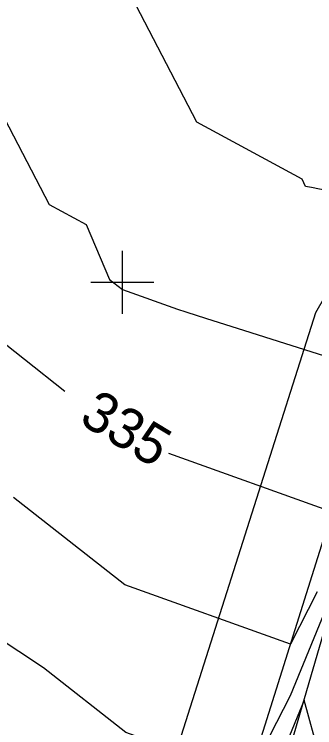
# Model space of a CAD drawing. Extents: x 487096 to 489566, y 221939 to 224454.
# Drawn here: x 488276.8 to 488300.7, y 223456 to 223512.7 of the extents above; entities that cross this region are included whole.
import ezdxf

# ---------------------------------------------------------------- set-up
doc = ezdxf.new("R2010")
doc.units = 0
for name, color, linetype in [('SV_BKLN_EARTH_TOP', 7, 'Continuous'), ('SV_SURF_INDEX_CONTOUR', 7, 'Continuous'), ('SV_SURF_INTER_CONTOUR', 7, 'Continuous'), ('SV_SURF_SPOT', 7, 'Continuous'), ('SV_WATR_INWETF', 7, 'Continuous'), ('SV_WATR_STREAM', 7, 'Continuous')]:
    doc.layers.add(name, color=color, linetype=linetype)

msp = doc.modelspace()

# ---------------------------------------------------------------- linework, layer by layer
at = {"layer": 'SV_BKLN_EARTH_TOP'}
msp.add_lwpolyline([(488285.935, 223421.955), (488304.8, 223481.874)], dxfattribs=at)
at = {"layer": 'SV_SURF_INDEX_CONTOUR'}
for points in [[(488233.223, 223552.139), (488238.155, 223549.446), (488243.978, 223536.925), (488255.675, 223514.417), (488267.055, 223492.613), (488274.354, 223487.789), (488280.81, 223482.721)], [(488289.043, 223477.783), (488302.048, 223473.132)]]:
    msp.add_lwpolyline(points, dxfattribs=at)
at = {"layer": 'SV_SURF_INTER_CONTOUR'}
for points in [[(488261.789, 223531.749), (488279.559, 223497.554), (488282.492, 223495.97), (488284.365, 223491.59), (488285.383, 223490.791), (488289.75, 223489.23), (488290.42, 223489.018), (488291.316, 223488.734), (488292.58, 223488.333), (488294.498, 223487.726), (488297.761, 223486.691), (488304.559, 223484.535)], [(488329.706, 223521.724), (488310.366, 223508.123), (488302.146, 223499.88), (488302.3, 223499.635), (488302.48, 223499.335), (488302.657, 223499.024), (488302.832, 223498.701), (488302.988, 223498.398), (488302.35, 223498.527), (488301.679, 223498.657), (488301.038, 223498.776), (488300.425, 223498.885), (488299.926, 223498.969), (488299.677, 223499.552), (488291.289, 223504.08), (488279.6, 223526.573)], [(488320.594, 223209.107), (488317.309, 223255.078), (488319.07, 223277.176), (488313.215, 223307.684), (488312.007, 223315.85), (488310.013, 223331.587), (488309.153, 223355.183), (488306.035, 223366.994), (488308.318, 223385.059), (488309.639, 223426.754), (488310.11, 223434.831), (488310.416, 223440.004), (488309.761, 223461.164), (488307.732, 223462.227), (488308.954, 223474.096), (488303.636, 223466.041), (488302.905, 223468.698), (488298.726, 223458.507), (488295.426, 223452.101), (488285.665, 223455.591), (488279.114, 223460.734), (488240.248, 223486.418)], [(488316.219, 223209.854), (488313.699, 223245.125), (488316.327, 223278.11), (488311.228, 223304.679), (488309.711, 223314.936), (488307.206, 223334.704), (488306.474, 223354.761), (488302.863, 223368.44), (488304.74, 223383.289), (488306.265, 223431.434), (488306.521, 223435.818), (488306.687, 223438.627), (488306.332, 223450.114), (488303.265, 223451.72), (488303.933, 223458.21), (488301.025, 223453.805), (488299.825, 223458.167), (488296.581, 223450.253), (488292.115, 223441.585), (488285.759, 223443.858), (488281.493, 223447.207), (488226.844, 223483.321)], [(488300.871, 223466.76), (488298.737, 223462.617), (488285.571, 223467.324), (488276.734, 223474.262)]]:
    msp.add_lwpolyline(points, dxfattribs=at)
at = {"layer": 'SV_SURF_SPOT'}
for p, q in [((488285.378, 223488.866), (488285.378, 223493.868)), ((488282.877, 223491.367), (488287.879, 223491.367)), ((488285.378, 223491.367), (488285.378, 223491.367))]:
    msp.add_line(p, q, dxfattribs=at)
at = {"layer": 'SV_WATR_INWETF'}
msp.add_lwpolyline([(488392.951, 223538.467), (488377.591, 223540.374), (488348.653, 223536.588), (488322.282, 223526.421), (488300.731, 223488.93), (488278.082, 223417.696)], dxfattribs=at)
at = {"layer": 'SV_WATR_STREAM'}
msp.add_lwpolyline([(488289.13, 223421.588), (488307.709, 223485.128)], dxfattribs=at)

# ---------------------------------------------------------------- texts
at = {"layer": 'SV_SURF_INDEX_CONTOUR'}
msp.add_text('335', height=3.2, rotation=329.0178, dxfattribs=at).set_placement((488281.826, 223480.238))

doc.saveas('drawing.dxf')
